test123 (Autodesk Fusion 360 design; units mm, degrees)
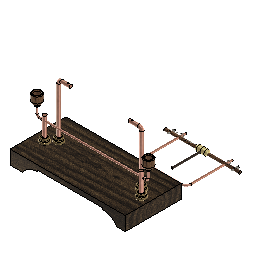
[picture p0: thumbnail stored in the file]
part number: 2025-06-23-16-23-19-648
part number: 2025-06-25-14-02-50-816
part number: 2025-06-25-16-29-36-569
part number: 2025-07-01-14-17-39-300
part number: 2025-07-01-14-19-18-271
part number: 2025-07-01-14-31-54-230
part number: 2025-07-01-14-31-54-261
part number: 2025-07-01-14-31-54-274
part number: 2025-07-01-14-31-54-285
part number: 2025-07-01-14-31-54-296
part number: 2025-07-01-14-31-54-306
part number: 2025-07-01-14-31-54-318
part number: 2025-07-01-14-31-54-340
part number: 2025-07-01-14-31-54-351
part number: 2025-07-01-14-31-54-363
part number: 2025-07-01-14-31-54-375
part number: 2025-07-01-14-31-54-387
part number: 2025-07-01-14-31-54-399
part number: 2025-07-01-14-31-54-411
box_primitive "BoxPrimitive2" DistanceX 60 DistanceY 120 DistanceZ 15 OffsetDistanceX 0 OffsetDistanceY 0 bodies "base"
hole "Hole1" HoleDepth 80 HoleDiameter 40 TipAngle 180
hole "Hole2" HoleDepth 80 HoleDiameter 40 TipAngle 180
box_primitive "BoxPrimitive3" DistanceX 7.439 DistanceY 69.412 DistanceZ -70 OffsetDistanceX 0 OffsetDistanceY 0
box_primitive "BoxPrimitive4" DistanceX 5 DistanceY 65 DistanceZ -75 OffsetDistanceX 0 OffsetDistanceY 0
copy_paste_bodies "CopyPasteBodies2"
copy_paste_bodies "CopyPasteBodies3"
move "Move3"
copy_paste_bodies "CopyPasteBodies4"
move "Move4"
copy_paste_bodies "CopyPasteBodies5"
move "Move5"
move "Move7"
move "Move8"
move "Move9"
move "Move10"
move "Move11"
move "Move12"
move "Move13"
move "Move14"
move "Move15"
move "Move16"
sketch "Sketch14" plane through (0, 0, 15) normal (0, 0, 1) x axis (-1, 0, 0)
  line L1 (60, -30) -> (-60, -30)
  line L2 (60, 30) -> (60, -30)
  line L3 (-60, 30) -> (60, 30)
  line L4 (-60, -30) -> (-60, 30)
  line L5 (-52, 5) -> (52, 5)
  line L6 (-45.2322, -2.7634) -> (44.7678, -2.7634)
  horizontal L5
  perpendicular L4 L6
move "Move17"
move "Move18"
move "Move19"
move "Move20"
move "Move21"
move "Move22"
cylinder_primitive "CylinderPrimitive6" Height 50 Diameter 4
sketch "Sketch17" plane through (0, 30, 0) normal (0, 1, 0) x axis (-1, 0, 0)
  line L1 (-30, 10) -> (-30, 8.1008)
  line L2 (35, 10) -> (-30, 10)
  line L3 (35, 8.5747) -> (35, 10)
  line L4 (60, 0) -> (50.8338, 0)
  line L5 (60, 15) -> (60, 0)
  line L6 (-60, 15) -> (60, 15)
  line L7 (-60, 0) -> (-60, 15)
  line L8 (-50.9344, 0) -> (-60, 0)
  arc A1 centre (34.4124, -11.4167) radius 20 clockwise from (35, 8.5747) to (50.8338, 0)
  arc A2 centre (-34.4932, -11.388) radius 20 clockwise from (-50.9344, 0) to (-30, 8.1008)
delete_face "DeleteFace2"
box_primitive "BoxPrimitive5" DistanceX 1.601 DistanceY 2.183 DistanceZ 50 OffsetDistanceX 0 OffsetDistanceY 0
box_primitive "BoxPrimitive6" DistanceX 1.601 DistanceY 16 DistanceZ 2 OffsetDistanceX 0 OffsetDistanceY 0
fillet "Fillet3" radius 1.15
fillet "Fillet4" radius 1.15
fillet "Fillet5" radius 1.1
fillet "Fillet6" radius 1.15
fillet "Fillet7" radius 1.15
fillet "Fillet8" radius 1.15
delete_face "DeleteFace3"
delete_face "DeleteFace6"
delete_face "DeleteFace7"
sketch "Sketch20" plane through (0, 30, 0) normal (0, 1, 0) x axis (-1, 0, 0)
  line L1 (-30, 10) -> (-30, 8.1008)
  line L2 (35, 10) -> (-30, 10)
  line L3 (35, 8.5747) -> (35, 10)
  line L4 (60, 0) -> (50.8338, 0)
  line L5 (60, 15) -> (60, 0)
  line L6 (-60, 15) -> (60, 15)
  line L7 (-60, 0) -> (-60, 15)
  line L8 (-50.9344, 0) -> (-60, 0)
  line L9 (-45, 91) -> (-45, 41)
  line L10 (-32, 94) -> (-42, 94)
  arc A1 centre (34.4124, -11.4167) radius 20 clockwise from (35, 8.5747) to (50.8338, 0)
  arc A2 centre (-34.4932, -11.388) radius 20 clockwise from (-50.9344, 0) to (-30, 8.1008)
  arc A3 centre (-42, 91) radius 3 clockwise from (-45, 91) to (-42, 94)
  vertical L9
  tangent L9 A3
  tangent A3 L10
  horizontal L10
pipe "Pipe1" SectionSize 3 SectionThickness 0.75 bodies "Rrod"
move "Move23"
copy_paste_bodies "CopyPasteBodies7"
move "Move24"
remove_body "RemoveBody1"
move "Move25"
cylinder_primitive "CylinderPrimitive7" Height 20 Diameter 3.3
offset_faces "OffsetFaces1" distance 0.3
component_from_bodies "Body->Comp1"
move "Move1"
box_primitive "BoxPrimitive7" DistanceX 10 DistanceY 5 DistanceZ -60 OffsetDistanceX 0 OffsetDistanceY 0
offset_faces "OffsetFaces2" distance 0.3
copy_paste_bodies "CopyPasteBodies8"
move "Move26"
sketch "Sketch24" plane through (0, 0, 0) normal (0, 1, 0) x axis (1, 0, 0)
sketch "Sketch25" plane through (-60, 0, 0) normal (-1, 0, 0) x axis (0, -1, 0)
  line L1 (-30, 0) -> (-30, 15)
  line L2 (30, 0) -> (-30, 0)
  line L3 (30, 15) -> (30, 0)
  line L4 (-30, 15) -> (30, 15)
cylinder_primitive "CylinderPrimitive8" sketch "Sketch25" Height 106 Diameter 2.5 bodies "wire1"
move "Move27"
move "Move28"
move "Move29"
move_face "MoveFace4"
offset_faces "OffsetFaces3" distance 6
offset_faces "OffsetFaces4" distance 0.3
offset_faces "OffsetFaces1" distance 0.3
offset_faces "OffsetFaces5" distance -0.3
sketch "Sketch27" plane through (0, 0, 0) normal (0, 1, 0) x axis (1, 0, 0)
hole "Hole3" HoleDepth 0.75 HoleDiameter 1.5 TipAngle 100
component_from_bodies "Body->Comp2"
sketch "Sketch29" plane through (0, -30, 0) normal (0, -1, 0) x axis (1, 0, 0)
  line L1 (35, 8.6056) -> (35, 10)
  line L2 (60, 0) -> (50.9344, 0)
  line L3 (60, 15) -> (60, 0)
  line L4 (-60, 15) -> (60, 15)
  line L5 (-60, 0) -> (-60, 15)
  line L6 (-50.8338, 0) -> (-60, 0)
  line L7 (-35, 10) -> (-35, 8.5747)
  line L8 (35, 10) -> (-35, 10)
  line L9 (57.5, 35) -> (55, 35)
  line L10 (60, 45) -> (60, 37.5)
  line L11 (-57.5, 35) -> (-55, 35)
  line L12 (-60, 45) -> (-60, 37.5)
  arc A1 centre (34.4932, -11.388) radius 20 clockwise from (35, 8.6056) to (50.9344, 0)
  arc A2 centre (-34.4124, -11.4167) radius 20 clockwise from (-50.8338, 0) to (-35, 8.5747)
  arc A3 centre (57.5, 37.5) radius 2.5 clockwise from (60, 37.5) to (57.5, 35)
  arc A4 centre (-57.5, 37.5) radius 2.5 clockwise from (-57.5, 35) to (-60, 37.5)
  horizontal L9
  tangent L9 A3
  tangent A3 L10
  vertical L10
  horizontal L11
  tangent L11 A4
  tangent A4 L12
  vertical L12
pipe "Pipe2" SectionSize 2 SectionThickness 0.625
sketch "Sketch31" plane through (0, -30, 0) normal (0, -1, 0) x axis (1, 0, 0)
  line L1 (35, 8.6056) -> (35, 10)
  line L2 (60, 0) -> (50.9344, 0)
  line L3 (60, 15) -> (60, 0)
  line L4 (-60, 15) -> (60, 15)
  line L5 (-60, 0) -> (-60, 15)
  line L6 (-50.8338, 0) -> (-60, 0)
  line L7 (-35, 10) -> (-35, 8.5747)
  line L8 (35, 10) -> (-35, 10)
  line L9 (57.5, 35) -> (55, 35)
  line L10 (60, 45) -> (60, 37.5)
  arc A1 centre (34.4932, -11.388) radius 20 clockwise from (35, 8.6056) to (50.9344, 0)
  arc A2 centre (-34.4124, -11.4167) radius 20 clockwise from (-50.8338, 0) to (-35, 8.5747)
  arc A3 centre (57.5, 37.5) radius 2.5 clockwise from (60, 37.5) to (57.5, 35)
  horizontal L9
  tangent L9 A3
  tangent A3 L10
  vertical L10
pipe "Pipe3" SectionSize 2 SectionThickness 0.625
hole "Hole4" HoleDepth 0.75 HoleDiameter 1.5 TipAngle 100
sketch "Sketch34" plane through (0, 0, 0) normal (0, 0, 1) x axis (1, 0, 0)
  line L1 (25, 55) -> (25, 95)
  line L2 (-20, 50) -> (20, 50)
  line L3 (-25, 95) -> (-25, 55)
  arc A1 centre (20, 55) radius 5 clockwise from (25, 55) to (20, 50)
  arc A2 centre (-20, 55) radius 5 clockwise from (-20, 50) to (-25, 55)
  vertical L1
  perpendicular L1 L2
  perpendicular L2 L3
  tangent L1 A1
  tangent L2 A2
pipe "Pipe4" SectionSize 2 SectionThickness 0.625 bodies "wire2"
move "Move30"
move "Move31"
offset_faces "OffsetFaces6" distance 5
offset_faces "OffsetFaces7" distance 5
cylinder_primitive "CylinderPrimitive9" sketch "Sketch25" Height 90 Diameter 3 bodies "wooden rod"
move "Move32"
move_face "MoveFace5"
offset_faces "OffsetFaces8" distance -9.5
move_face "MoveFace6"
move_face "MoveFace7"
extrude "Extrude2" add sketch "Sketch25" along normal blind 4
sketch "Sketch41" plane through (0, 0, 0) normal (1, 0, 0) x axis (0, 1, 0)
move_face "MoveFace8"
move_face "MoveFace9"
sketch "Sketch43" plane through (0, -30, 0) normal (0, -1, 0) x axis (1, 0, 0)
  line L1 (35, 8.6056) -> (35, 10)
  line L2 (60, 0) -> (50.9344, 0)
  line L3 (60, 15) -> (60, 0)
  line L4 (-64, 15) -> (60, 15)
  line L5 (-64, 0) -> (-64, 15)
  line L6 (-50.8338, 0) -> (-64, 0)
  line L7 (-35, 10) -> (-35, 8.5747)
  line L8 (35, 10) -> (-35, 10)
  line L9 (0, 98) -> (-1, 95)
  line L10 (0, 97.1928) -> (-0.7309, 95)
  line L11 (0, 98) -> (0, 97.1928)
  line L12 (-0.7309, 95) -> (-1, 95)
  arc A1 centre (34.4932, -11.388) radius 20 clockwise from (35, 8.6056) to (50.9344, 0)
  arc A2 centre (-34.4124, -11.4167) radius 20 clockwise from (-50.8338, 0) to (-35, 8.5747)
  parallel L9 L10
  vertical L11
  horizontal L12
revolve "Revolve2" sketch "Sketch43" AlongAngle 360 bodies "cone-pivot"
move "Move33"
move "Move34"
move_face "MoveFace10"
offset_faces "OffsetFaces9" distance 0.8
move_face "MoveFace11"
move "Move35"
move_face "MoveFace12"
move_face "MoveFace13"
cylinder_primitive "CylinderPrimitive11" Height 5.5 Diameter 1.478
copy_paste_bodies "CopyPasteBodies9"
move "Move36"
move_face "MoveFace14"
move_face "MoveFace15"
delete_face "DeleteFace8"
cylinder_primitive "CylinderPrimitive12" Height 5 Diameter 1.5
move_face "MoveFace16"
move_face "MoveFace17"
move_face "MoveFace18" TranslateX 0 TranslateY 0 TranslateZ 18
move "Move37" TranslateX -44.3 TranslateY 139 TranslateZ 62
copy_paste_bodies "CopyPasteBodies10"
move "Move38"
sketch "Sketch50" plane through (0, 0, 0) normal (0, 0, 1) x axis (1, 0, 0)
move_face "MoveFace40"
move_face "MoveFace41"
move_face "MoveFace42"
move_face "MoveFace43"
move_face "MoveFace44"
move_face "MoveFace45"
move_face "MoveFace46"
move_face "MoveFace47"
move_face "MoveFace48"
cylinder_primitive "CylinderPrimitive14" Height 9.1 Diameter 0.385
move_face "MoveFace49"
step "TorusPrimitive5" MinorDiameter 0.75 MajorDiameter 2
move_face "MoveFace50"
move_face "MoveFace51"
step "TorusPrimitive6" MinorDiameter 0.75 MajorDiameter 1.5
move_face "MoveFace54"
copy_paste_bodies "CopyPasteBodies16"
move "Move53"
move_face "MoveFace55"
copy_paste_bodies "CopyPasteBodies17"
move "Move54"
copy_paste_bodies "CopyPasteBodies18"
move "Move55"
move_face "MoveFace56"
move "Move56"
move_face "MoveFace57"
cylinder_primitive "CylinderPrimitive16" Height 35 Diameter 2
move "Move57"
cylinder_primitive "CylinderPrimitive17" Height 7 Diameter 6
move_face "MoveFace62"
move_face "MoveFace63"
move_face "MoveFace64" TranslateX 3.5 TranslateY -1 TranslateZ 0
fillet "Fillet9" radius 3
cylinder_primitive "CylinderPrimitive18" Height -7 Diameter 6
move_face "MoveFace65" TranslateX 0 TranslateY 8.8 TranslateZ -3
move_face "MoveFace66" TranslateX 0 TranslateY 0.2 TranslateZ 0
move_face "MoveFace67" TranslateX 0 TranslateY 0.2 TranslateZ 0
fillet "Fillet10" radius 3
move_face "MoveFace68" TranslateX 0 TranslateY 0 TranslateZ 0.1
cylinder_primitive "CylinderPrimitive19" Height 2 Diameter 5
fillet "Fillet11" radius 0.8
copy_paste_bodies "CopyPasteBodies19"
move "Move58"
cylinder_primitive "CylinderPrimitive20" Height 10 Diameter 10
fillet "Fillet12" radius 3
fillet "Fillet13" radius 0.5
copy_paste_bodies "CopyPasteBodies20"
move "Move59"
cylinder_primitive "CylinderPrimitive21" Height -7 Diameter 6.5
fillet "Fillet14" radius 0.75
cylinder_primitive "CylinderPrimitive22" Height -7 Diameter 6.5
fillet "Fillet15" radius 0.75
component_insert "Component Insert"
remove_instance "RemoveInstance1"
component_from_bodies "Body->Comp3"
component_from_bodies "Body->Comp4"
component_from_bodies "Body->Comp5"
component_from_bodies "Body->Comp6"
component_from_bodies "Body->Comp7"
component_from_bodies "Body->Comp8"
component_from_bodies "Body->Comp9"
component_from_bodies "Body->Comp11"
component_from_bodies "Body->Comp12"
component_from_bodies "Body->Comp13"
component_from_bodies "Body->Comp14"
component_from_bodies "Body->Comp15"
component_from_bodies "Body->Comp16"
component_from_bodies "Body->Comp17"
as_built_joint "As-built1"
joint "Assemble1" alignAngle 0 alignOffsetX 0 alignOffsetY 0 alignOffsetZ 0 RotateRest 0 RotateMinimum -25 RotateMaximum 25
move "Move1"
move "Move2"
extrude "Extrude1" add of existing geometry blind 0.15
extrude "Extrude2" add of existing geometry blind 0.3
copy_paste_bodies "CutPasteBodies"
copy_paste_bodies "CopyPasteBodies22"
move_face "MoveFace69"
cylinder_primitive "CylinderPrimitive25" Height 2 Diameter 4
move "Move61"
fillet "Fillet16" radius 1
copy_paste_bodies "CopyPasteBodies23"
move "Move62"
move_face "MoveFace70"
delete_face "DeleteFace1"
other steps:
base_feature "Base Feature1"
base_feature "Base Feature1" bodies "Lrod"
base_feature "Base Feature1"
move "Move1"
move "Move2"
base_feature "Base Feature1"
base_feature "Base Feature1" bodies "wire2"
base_feature "Base Feature1" bodies "wooden rod"
base_feature "Base Feature1" bodies "cone-pivot"
base_feature "Base Feature1"
base_feature "Base Feature1"
base_feature "Base Feature1"
base_feature "Base Feature1"
base_feature "Base Feature1"
base_feature "Base Feature1"
base_feature "Base Feature1"
base_feature "Base Feature1"
move "Move1"
move "Move1"
move "Move1"
move "Move1"
move "Move1"
move "Move1"
move "Move1"
move "Move1"
move "Move1"
move "Move1"
move "Move1"
move "Move2"
move "Move2"
move "Move2"
move "Move2"
move "Move2"
move "Move2"
move "Move2"
move "Move2"
move "Move2"
move "Move2"
move "Move2"
base_feature "Base Feature1" bodies "cone-pivot (1)"
move "Move1"
move "Move2"
base_feature "Base Feature2" bodies "L1"
base_feature "Base Feature3" bodies "L2"
base_feature "Base Feature4" bodies "R2"
base_feature "Base Feature5" bodies "R1"
base_feature "Base Feature7" bodies "Lrod"
base_feature "Base Feature8"
base_feature "Base Feature9" bodies "cone-pivot", "cone-pivot (1)"
base_feature "Base Feature10"
base_feature "Base Feature16"
base_feature "Base Feature17"
base_feature "Base Feature18"
base_feature "Base Feature19"
base_feature "Base Feature20"
base_feature "Base Feature21" bodies "Lrod"
base_feature "Base Feature22" bodies "base", "L2", "R1", "L1", "R2", "wire1", "Rrod"
base_feature "Base Feature23"
create_component "CreateComponent1"
remove_body "RemoveBody2"
create_component "CreateComponent2"
remove_body "RemoveBody3"
create_component "CreateComponent4"
create_component "CreateComponent5"
create_component "CreateComponent6"
remove_body "RemoveBody4"
create_component "CreateComponent7"
remove_body "RemoveBody5"
create_component "CreateComponent8"
remove_body "RemoveBody6"
create_component "CreateComponent9"
remove_body "RemoveBody7"
create_component "CreateComponent10"
remove_body "RemoveBody8"
create_component "CreateComponent11"
remove_body "RemoveBody9"
create_component "CreateComponent12"
remove_body "RemoveBody10"
create_component "CreateComponent14"
remove_body "RemoveBody12"
create_component "CreateComponent15"
remove_body "RemoveBody13"
create_component "CreateComponent16"
remove_body "RemoveBody14"
create_component "CreateComponent17"
remove_body "RemoveBody15"
create_component "CreateComponent18"
remove_body "RemoveBody16"
create_component "CreateComponent19"
remove_body "RemoveBody17"
create_component "CreateComponent20"
remove_body "RemoveBody18"
joint_origin "JointOrigin6"
joint_origin "JointOrigin7"
remove_body "RemoveBody1"
named bodies: "base", "L1", "L2", "R2", "R1", "Rrod", "Lrod", "wire1", "wire2", "wooden rod", "cone-pivot", "cone-pivot (1)", "Lrod (1)", "base (2)", "L2 (1)", "R1 (1)", "L1 (1)", "R2 (1)", "wire1 (1)", "Rrod (1)"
